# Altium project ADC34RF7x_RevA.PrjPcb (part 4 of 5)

## Sheet ADC34RF7x_Power3_RevA.SchDoc: EVM Power 3
size 431 x 279 mm; Date: Not shown in title block; ApprovedBy: Not shown in title block; CheckedBy: Not shown in title block; Author: Not shown in title block; CompanyName: Not shown in title block; DrawnBy: CW; Engineer: Not shown in title block; Organization: Not shown in title block; Address1: Not shown in title block; Address2: Not shown in title block; Address3: Not shown in title block; Address4: Not shown in title block; DocumentNumber: 7; Revision: Use project parameter SCH_Rev; SheetNumber: 15; SheetTotal: 19; PageSetup: Record=PageOptions¦CenterHorizontal=True¦CenterVertical=True¦PrintScale=1.00¦XCorrection=1.00¦YCorrection=1.00¦PrintKind=0¦BorderSize=5000000¦LeftOffset=0¦BottomOffset=0¦Orientation=2¦PaperLength=1000¦PaperWidth=1000¦Scale=100¦PaperSource=15¦PrintQuality=600¦MediaType=1¦DitherType=10¦PaperKind=Letter¦PrintScaleMode=1
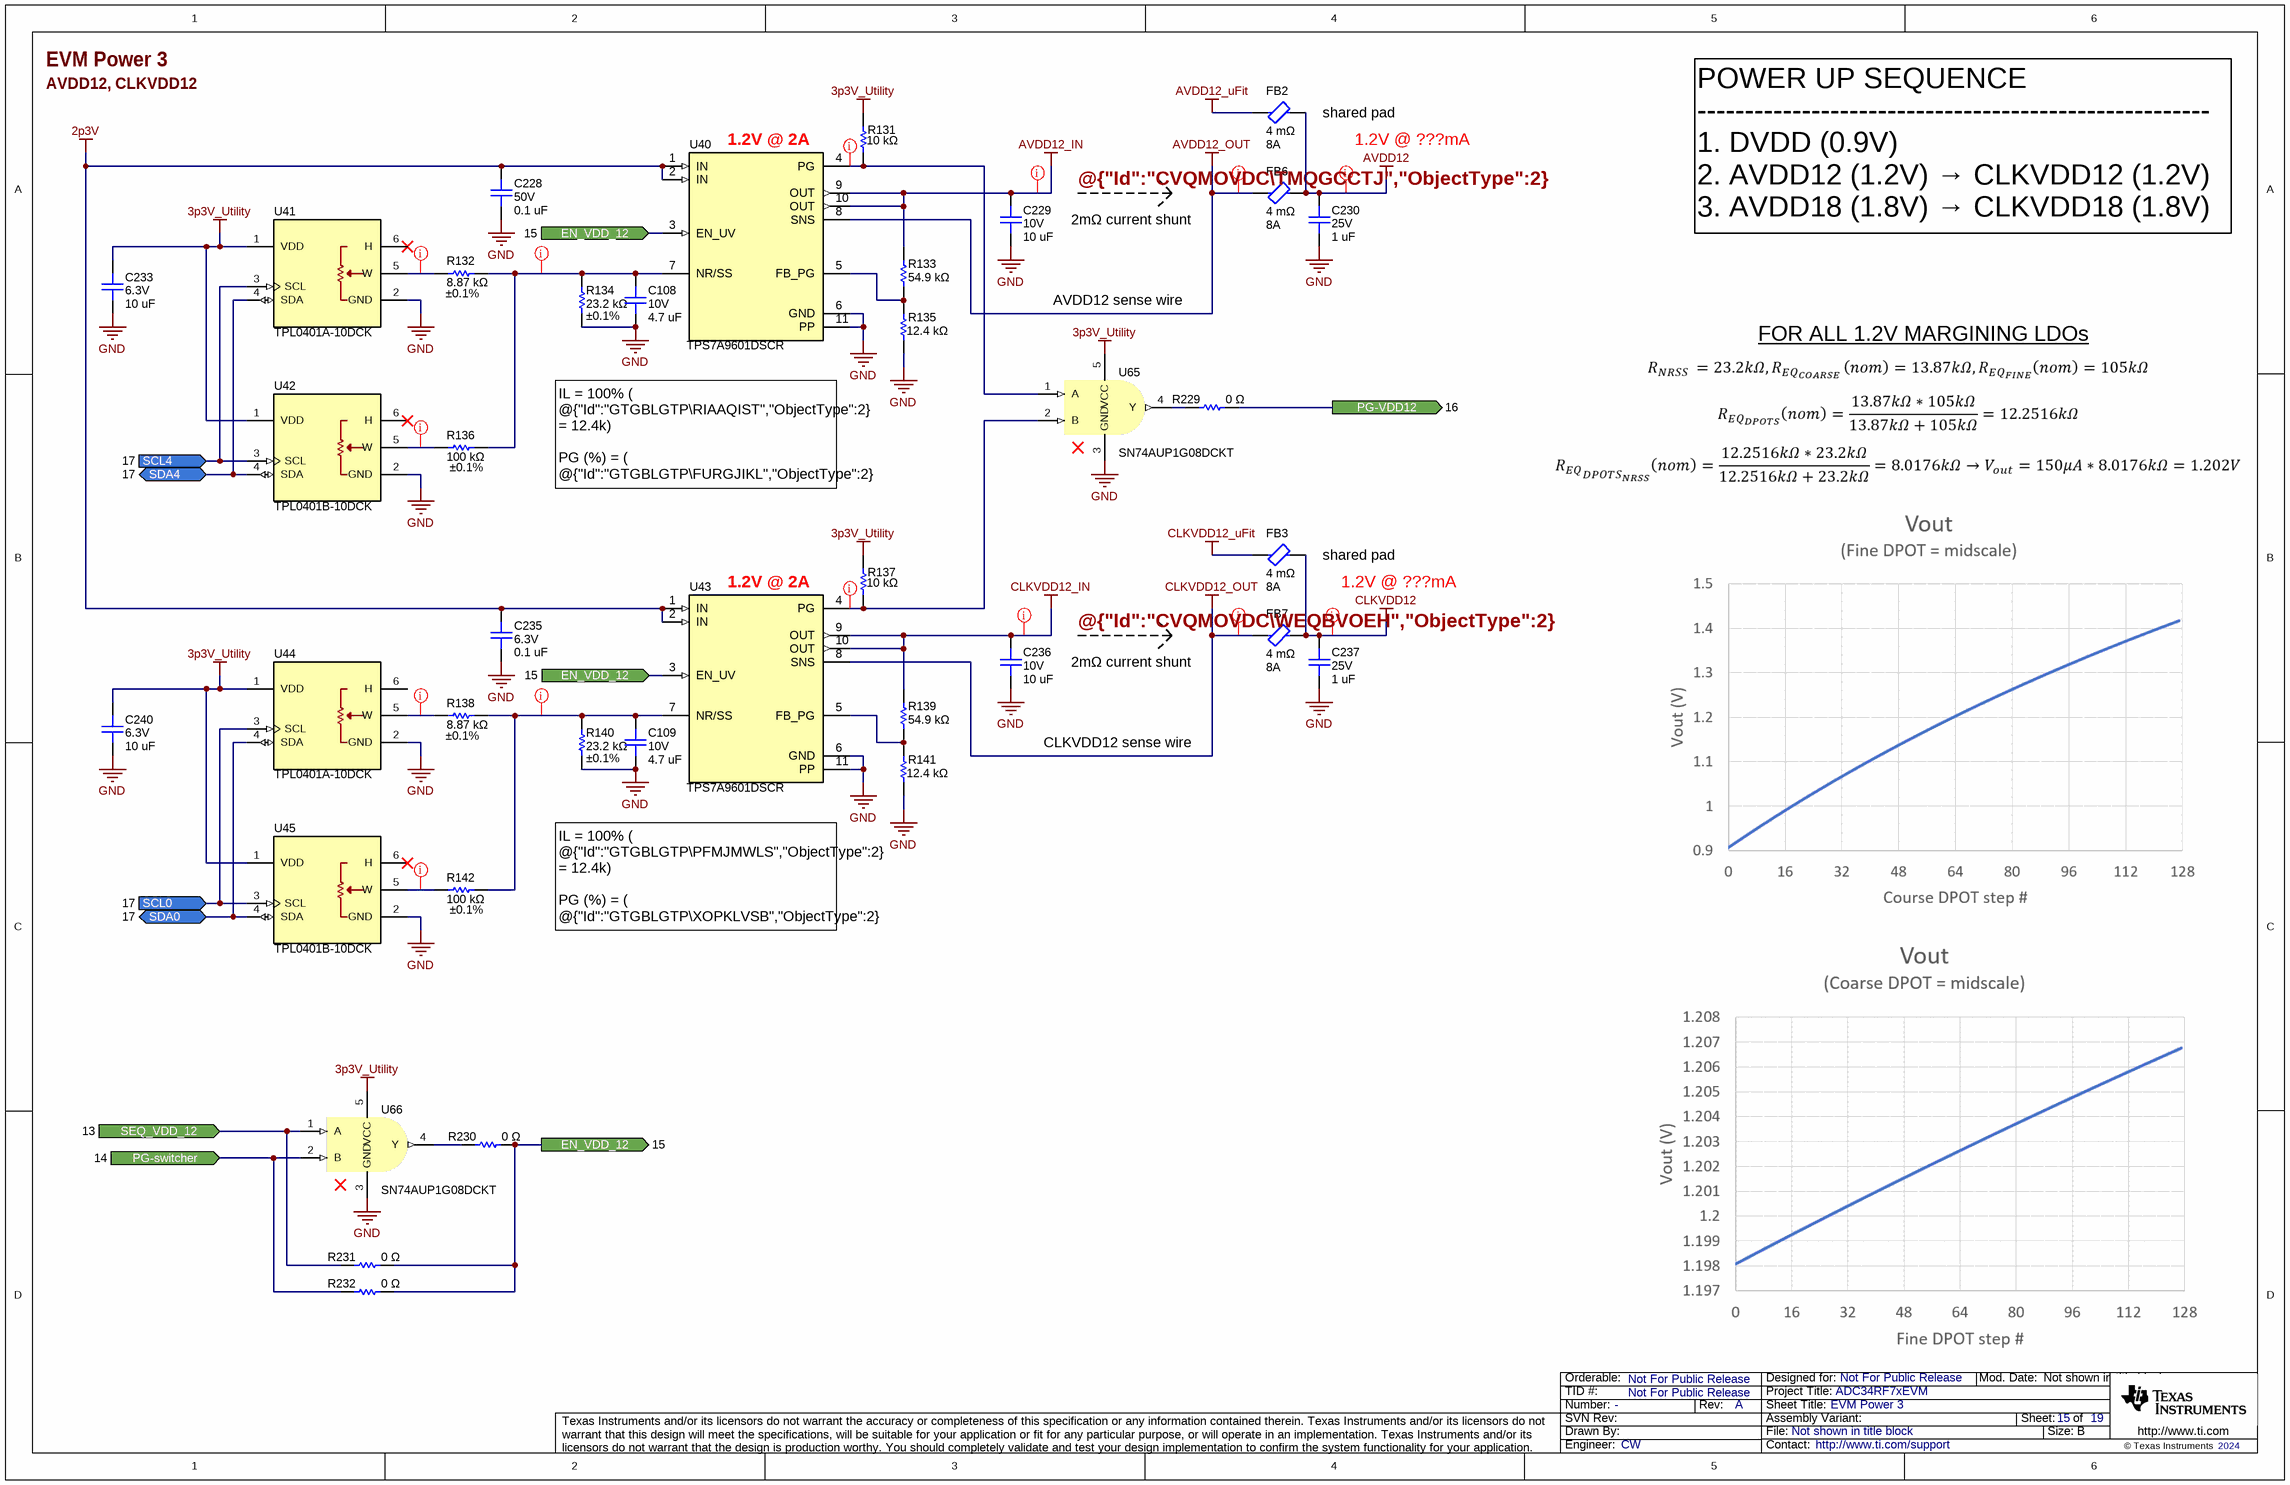
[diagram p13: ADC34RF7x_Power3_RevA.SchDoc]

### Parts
C108  value 4.7 uF  Voltage - Rated: 10V  [0402L_cap]  (hidden comment: C1005X5R1A475K050BE)
C109  value 4.7 uF  Voltage - Rated: 10V  [0402L_cap]  (hidden comment: C1005X5R1A475K050BE)
C228  value 0.1 uF  Voltage - Rated: 50V  [0402L_cap]  (hidden comment: C1005X5R1H104K050BB)
C229  value 10 uF  Voltage - Rated: 10V  [0603L_cap]  (hidden comment: 0603ZD106KAT2A)
C230  value 1 uF  Voltage - Rated: 25V  [0402L_cap]  (hidden comment: C1005X5R1E105K050BC)
C233  value 10 uF  Voltage - Rated: 6.3V  [0402L_cap]  (hidden comment: GRM155C80J106ME11D)
C235  value 0.1 uF  Voltage - Rated: 6.3V  [0402L_cap]  (hidden comment: 04026D104KAT4A)
C236  value 10 uF  Voltage - Rated: 10V  [0603L_cap]  (hidden comment: 0603ZD106KAT2A)
C237  value 1 uF  Voltage - Rated: 25V  [0402L_cap]  (hidden comment: C1005X5R1E105K050BC)
C240  value 10 uF  Voltage - Rated: 6.3V  [0402L_cap]  (hidden comment: GRM155C80J106ME11D)
FB2  Current: 8A  DCR: 4 mΩ  [0603L]  (hidden comment: BLE18PS080SN1D)
FB3  Current: 8A  DCR: 4 mΩ  [0603L]  (hidden comment: BLE18PS080SN1D)
FB6  Current: 8A  DCR: 4 mΩ  [0603L]  (hidden comment: BLE18PS080SN1D)
FB7  Current: 8A  DCR: 4 mΩ  [0603L]  (hidden comment: BLE18PS080SN1D)
R131  value 10 kΩ  [0402L]  (hidden comment: ERJ-PA2F1002X)
R132  value 8.87 kΩ  Tolerance: ±0.1%  [0402L]  (hidden comment: ERA-2AEB8871X)
R133  value 54.9 kΩ  [0402L]  (hidden comment: ERJ-2RKF5492X)
R134  value 23.2 kΩ  Tolerance: ±0.1%  [0402L]  (hidden comment: ERA-2ARB2322X)
R135  value 12.4 kΩ  [0402L]  (hidden comment: ERJ-2RKF1242X)
R136  value 100 kΩ  Tolerance: ±0.1%  [0402L]  (hidden comment: ERA-2AEB104X)
R137  value 10 kΩ  [0402L]  (hidden comment: ERJ-PA2F1002X)
R138  value 8.87 kΩ  Tolerance: ±0.1%  [0402L]  (hidden comment: ERA-2AEB8871X)
R139  value 54.9 kΩ  [0402L]  (hidden comment: ERJ-2RKF5492X)
R140  value 23.2 kΩ  Tolerance: ±0.1%  [0402L]  (hidden comment: ERA-2ARB2322X)
R141  value 12.4 kΩ  [0402L]  (hidden comment: ERJ-2RKF1242X)
R142  value 100 kΩ  Tolerance: ±0.1%  [0402L]  (hidden comment: ERA-2AEB104X)
R229  value 0 Ω  [0402L]  (hidden comment: ERJ-2GE0R00X)
R230  value 0 Ω  [0402L]  (hidden comment: ERJ-2GE0R00X)
R231  value 0 Ω  [0402L]  (hidden comment: ERJ-2GE0R00X)
R232  value 0 Ω  [0402L]  (hidden comment: ERJ-2GE0R00X)
U40  PartNumber: TPS7A9601DSCR  [DRC0010J]  (hidden comment: TPS7A9601DSC)
U41  TPL0401A-10DCK  [DCK0006A]
U42  TPL0401B-10DCK  [DCK0006A]
U43  PartNumber: TPS7A9601DSCR  [DRC0010J]  (hidden comment: TPS7A9601DSC)
U44  TPL0401A-10DCK  [DCK0006A]
U45  TPL0401B-10DCK  [DCK0006A]
U65  SN74AUP1G08DCKT  [DCK0005A]
U66  SN74AUP1G08DCKT  [DCK0005A]

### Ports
EN_VDD_12 (in, see 15), EN_VDD_12 (out, see 15), PG-switcher (in, see 14), PG-VDD12 (out, see 16), SCL0 (in, see 17), SCL4 (in, see 17), SDA0 (bidir, see 17), SDA4 (bidir, see 17), SEQ_VDD_12 (in, see 13)

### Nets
2p3V: C228.2 C235.2 U40.1(IN) U40.2(IN) U43.1(IN) U43.2(IN)
3p3V_Utility: C233.2 C240.2 R131.2 R137.2 U41.1(VDD) U42.1(VDD) U44.1(VDD) U45.1(VDD) U65.5(VCC) U66.5(VCC)
AVDD12: C230.2 FB2.2 FB6.2
AVDD12_IN: C229.2 R133.2 U40.9(OUT) U40.10(OUT)
AVDD12_OUT: FB6.1 U40.8(SNS)
AVDD12_uFit: FB2.1
CLKVDD12: C237.2 FB3.2 FB7.2
CLKVDD12_IN: C236.2 R139.2 U43.9(OUT) U43.10(OUT)
CLKVDD12_OUT: FB7.1 U43.8(SNS)
CLKVDD12_uFit: FB3.1
GND: C108.2 C109.2 C228.1 C229.1 C230.1 C233.1 C235.1 C236.1 C237.1 C240.1 R134.1 R135.1 R140.1 R141.1 U40.6(GND) U40.11(PP) U41.2(GND) U42.2(GND) U43.6(GND) U43.11(PP) U44.2(GND) U45.2(GND) U65.3(GND) U66.3(GND)
EN_VDD_12: R230.2 R231.2 R232.2 U40.3(EN_UV) U43.3(EN_UV) ; port EN_VDD_12
PG-switcher: R232.1 U66.2(B) ; port PG-switcher
PG-VDD12: R229.2 ; port PG-VDD12
SCL0: U44.3(SCL) U45.3(SCL) ; port SCL0
SCL4: U41.3(SCL) U42.3(SCL) ; port SCL4
SDA0: U44.4(SDA) U45.4(SDA) ; port SDA0
SDA4: U41.4(SDA) U42.4(SDA) ; port SDA4
SEQ_VDD_12: R231.1 U66.1(A) ; port SEQ_VDD_12
NetC108_1: C108.1 R132.2 R134.2 R136.2 U40.7(NR/SS)
NetC109_1: C109.1 R138.2 R140.2 R142.2 U43.7(NR/SS)
NetR131_1: R131.1 U40.4(PG) U65.1(A)
NetR132_1: R132.1 U41.5(W)
NetR133_1: R133.1 R135.2 U40.5(FB_PG)
NetR136_1: R136.1 U42.5(W)
NetR137_1: R137.1 U43.4(PG) U65.2(B)
NetR138_1: R138.1 U44.5(W)
NetR139_1: R139.1 R141.2 U43.5(FB_PG)
NetR142_1: R142.1 U45.5(W)
NetR229_1: R229.1 U65.4(Y)
NetR230_1: R230.1 U66.4(Y)

Not connected (* = marked no-connect by the designer): U41 6(H)*; U42 6(H)*; U44 6(H); U45 6(H)*

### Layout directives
net class Power_AVDD12: AVDD12, AVDD12_IN, AVDD12_OUT
net class Power_CLKVDD12: CLKVDD12, CLKVDD12_IN, CLKVDD12_OUT
net class Power sequencing: NetR131_1, NetR137_1
net class Margining: NetC108_1, NetC109_1, NetR132_1, NetR136_1, NetR138_1, NetR142_1

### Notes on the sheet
- AVDD12, CLKVDD12
- (near U40) 1.2V @ 2A
- (near FB2) shared pad
- 1.2V @ ???mA
- @{"Id":"CVQMOVDC\TMQGCCTJ","ObjectType":2}
- 2mΩ current shunt
- POWER UP SEQUENCE
  ------------------------------------------------------
  1. DVDD (0.9V)
  2. AVDD12 (1.2V) → CLKVDD12 (1.2V)
  3. AVDD18 (1.8V) → CLKVDD18 (1.8V)
- AVDD12 sense wire
- FOR ALL 1.2V MARGINING LDOs
- IL = 100% ( @{"Id":"GTGBLGTP\RIAAQIST","ObjectType":2} = 12.4k)
  PG (%) = ( @{"Id":"GTGBLGTP\FURGJIKL","ObjectType":2} / @{"Id":"GTGBLGTP\RIAAQIST","ObjectType":2} +1)*(0.2V/1.2V)
  PG (%) = (54.9k/12.4k+1)*(0.2V/1.2V)
  PG = 90.4%
- (near FB3) shared pad
- (near U43) 1.2V @ 2A
- @{"Id":"CVQMOVDC\WEQBVOEH","ObjectType":2}
- CLKVDD12 sense wire
- IL = 100% ( @{"Id":"GTGBLGTP\PFMJMWLS","ObjectType":2} = 12.4k)
  PG (%) = ( @{"Id":"GTGBLGTP\XOPKLVSB","ObjectType":2} / @{"Id":"GTGBLGTP\PFMJMWLS","ObjectType":2} +1)*(0.2V/1.2V)
  PG (%) = (54.9k/12.4k+1)*(0.2V/1.2V)
  PG = 90.4%

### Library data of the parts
C108 C109 = capcc03139: CAP CER 4.7UF 10V X5R 0402; Manufacturer: TDK Corporation; CompType: Capacitor Ceramic; Tolerance: ±10%; SizeX_mm: 1; SizeY_mm: 0.5; SizeZ_mm: 0.7
C228 = capcc01268: CAP CER 0.1UF 50V X5R 0402; Manufacturer: TDK Corporation; CompType: Capacitor Ceramic; Tolerance: ±10%; SizeX_mm: 1; SizeY_mm: 0.5; SizeZ_mm: 0.55
C229 C236 = capcc03657: CAP CER 10UF 10V X5R 0603; Manufacturer: KYOCERA AVX; CompType: Capacitor Ceramic; Tolerance: ±10%; SizeX_mm: 1.6; SizeY_mm: 0.81; SizeZ_mm: 0.94
C230 C237 = capcc02750: CAP CER 1UF 25V X5R 0402; Manufacturer: TDK Corporation; CompType: Capacitor Ceramic; Tolerance: ±10%; SizeX_mm: 1; SizeY_mm: 0.5; SizeZ_mm: 0.55
C233 C240 = capcc09398: CAP CER 10UF 6.3V X6S 0402; Manufacturer: Murata; CompType: Capacitor Ceramic; Tolerance: ±20%; SizeX_mm: 1; SizeY_mm: 0.5; SizeZ_mm: 0.7
C235 = capcc01277: CAP CER 0.1UF 6.3V X5R 0402; Manufacturer: KYOCERA AVX; CompType: Capacitor Ceramic; Tolerance: ±10%; SizeX_mm: 1; SizeY_mm: 0.5
FB2 FB3 FB6 FB7 = dcp00004: 8.5 Ohms @ 100 MHz 1 Power Line Ferrite Bead 0603 (1608 Metric) 8A 4mOhm; Manufacturer: Murata; Impedance: 8.5 Ω; SizeX_mm: 1.6; SizeY_mm: 0.8
R131 R137 = RSMD040200311: RES SMD 10K OHM 1% 1/5W 0402; Manufacturer: Panasonic Electronic Components; SizeX_mm: 1; SizeY_mm: 0.5; SizeZ_mm: 0.4; CompType: Resistor SMD; Power (Watts): 0.2W, 1/5W; Temperature Coefficient: ±100ppm/°C
R132 R138 = RSMD040203743: RES SMD 8.87KOHM 0.1% 1/16W 0402; Manufacturer: Panasonic Electronic Components; CompType: Resistor SMD; Power (Watts): 0.063W, 1/16W; Temperature Coefficient: ±25ppm/°C; SizeX_mm: 1; SizeY_mm: 0.5; SizeZ_mm: 0.4
R133 R139 = RSMD040203107: RES SMD 54.9K OHM 1% 1/10W 0402; Manufacturer: Panasonic Electronic Components; CompType: Resistor SMD; Power (Watts): 0.1W, 1/10W; Temperature Coefficient: ±100ppm/°C; SizeX_mm: 1; SizeY_mm: 0.5; SizeZ_mm: 0.4
R134 R140 = RSMD040201567: RES SMD 23.2KOHM 0.1% 1/16W 0402; Manufacturer: Panasonic Electronic Components; CompType: Resistor SMD; Power (Watts): 0.063W, 1/16W; Temperature Coefficient: ±10ppm/°C; SizeX_mm: 1; SizeY_mm: 0.5; SizeZ_mm: 0.4
R135 R141 = RSMD040200547: RES SMD 12.4K OHM 1% 1/10W 0402; Manufacturer: Panasonic Electronic Components; CompType: Resistor SMD; Power (Watts): 0.1W, 1/10W; Temperature Coefficient: ±100ppm/°C; SizeX_mm: 1; SizeY_mm: 0.5; SizeZ_mm: 0.4
R136 R142 = RSMD040200357: RES SMD 100K OHM 0.1% 1/16W 0402; Manufacturer: Panasonic Electronic Components; CompType: Resistor SMD; Power (Watts): 0.063W, 1/16W; Temperature Coefficient: ±25ppm/°C; SizeX_mm: 1; SizeY_mm: 0.5; SizeZ_mm: 0.4
R229-R232 = RSMD040200001: RES SMD 0 OHM JUMPER 1/10W 0402; Manufacturer: Panasonic Electronic Components; CompType: Resistor SMD; Power (Watts): 0.1W, 1/10W; SizeX_mm: 1; SizeY_mm: 0.5; SizeZ_mm: 0.4
U40 U43 = cmp00446: 2-A, ultra-low noise ultra-high PSRR RF voltage regulator; Manufacturer: Texas Instruments; CompType: LDO
U41 U44 = TPL0401A-10DCK: 128-tap single-channel digital potentiometer (digipot) with I2C interface (address 0101110); Alternate PartNumber: TPL0401A-10DCKT; Manufacturer: Texas Instruments; SymbolCreator: Altium; SizeArea_mm2: 4.2; SizeAreaWB_mm2: 9.3; U/M: EA; UniqueID: cmp00230
U42 U45 = TPL0401B-10DCK: 128-tap single-channel digital potentiometer (digipot) with I2C interface (address 0111110); Alternate PartNumber: TPL0401B-10DCKT; Manufacturer: Texas Instruments; SymbolCreator: Altium; SizeArea_mm2: 4.2; SizeAreaWB_mm2: 9.3; U/M: EA; UniqueID: cmp00231
U65 U66 = cmp00268: SN74AUP1G08 Low-Power Single 2-Input Positive-AND Gate; Manufacturer: Texas Instruments

## Sheet ADC34RF7x_Power4_RevA.SchDoc: EVM Power 4
size 431 x 279 mm; Date: Not shown in title block; ApprovedBy: Not shown in title block; CheckedBy: Not shown in title block; Author: Not shown in title block; CompanyName: Not shown in title block; DrawnBy: CW; Engineer: Not shown in title block; Organization: Not shown in title block; Address1: Not shown in title block; Address2: Not shown in title block; Address3: Not shown in title block; Address4: Not shown in title block; DocumentNumber: 8; Revision: Use project parameter SCH_Rev; SheetNumber: 16; SheetTotal: 19; PageSetup: Record=PageOptions¦CenterHorizontal=True¦CenterVertical=True¦PrintScale=1.00¦XCorrection=1.00¦YCorrection=1.00¦PrintKind=0¦BorderSize=5000000¦LeftOffset=0¦BottomOffset=0¦Orientation=2¦PaperLength=1000¦PaperWidth=1000¦Scale=100¦PaperSource=15¦PrintQuality=600¦MediaType=1¦DitherType=10¦PaperKind=Letter¦PrintScaleMode=1
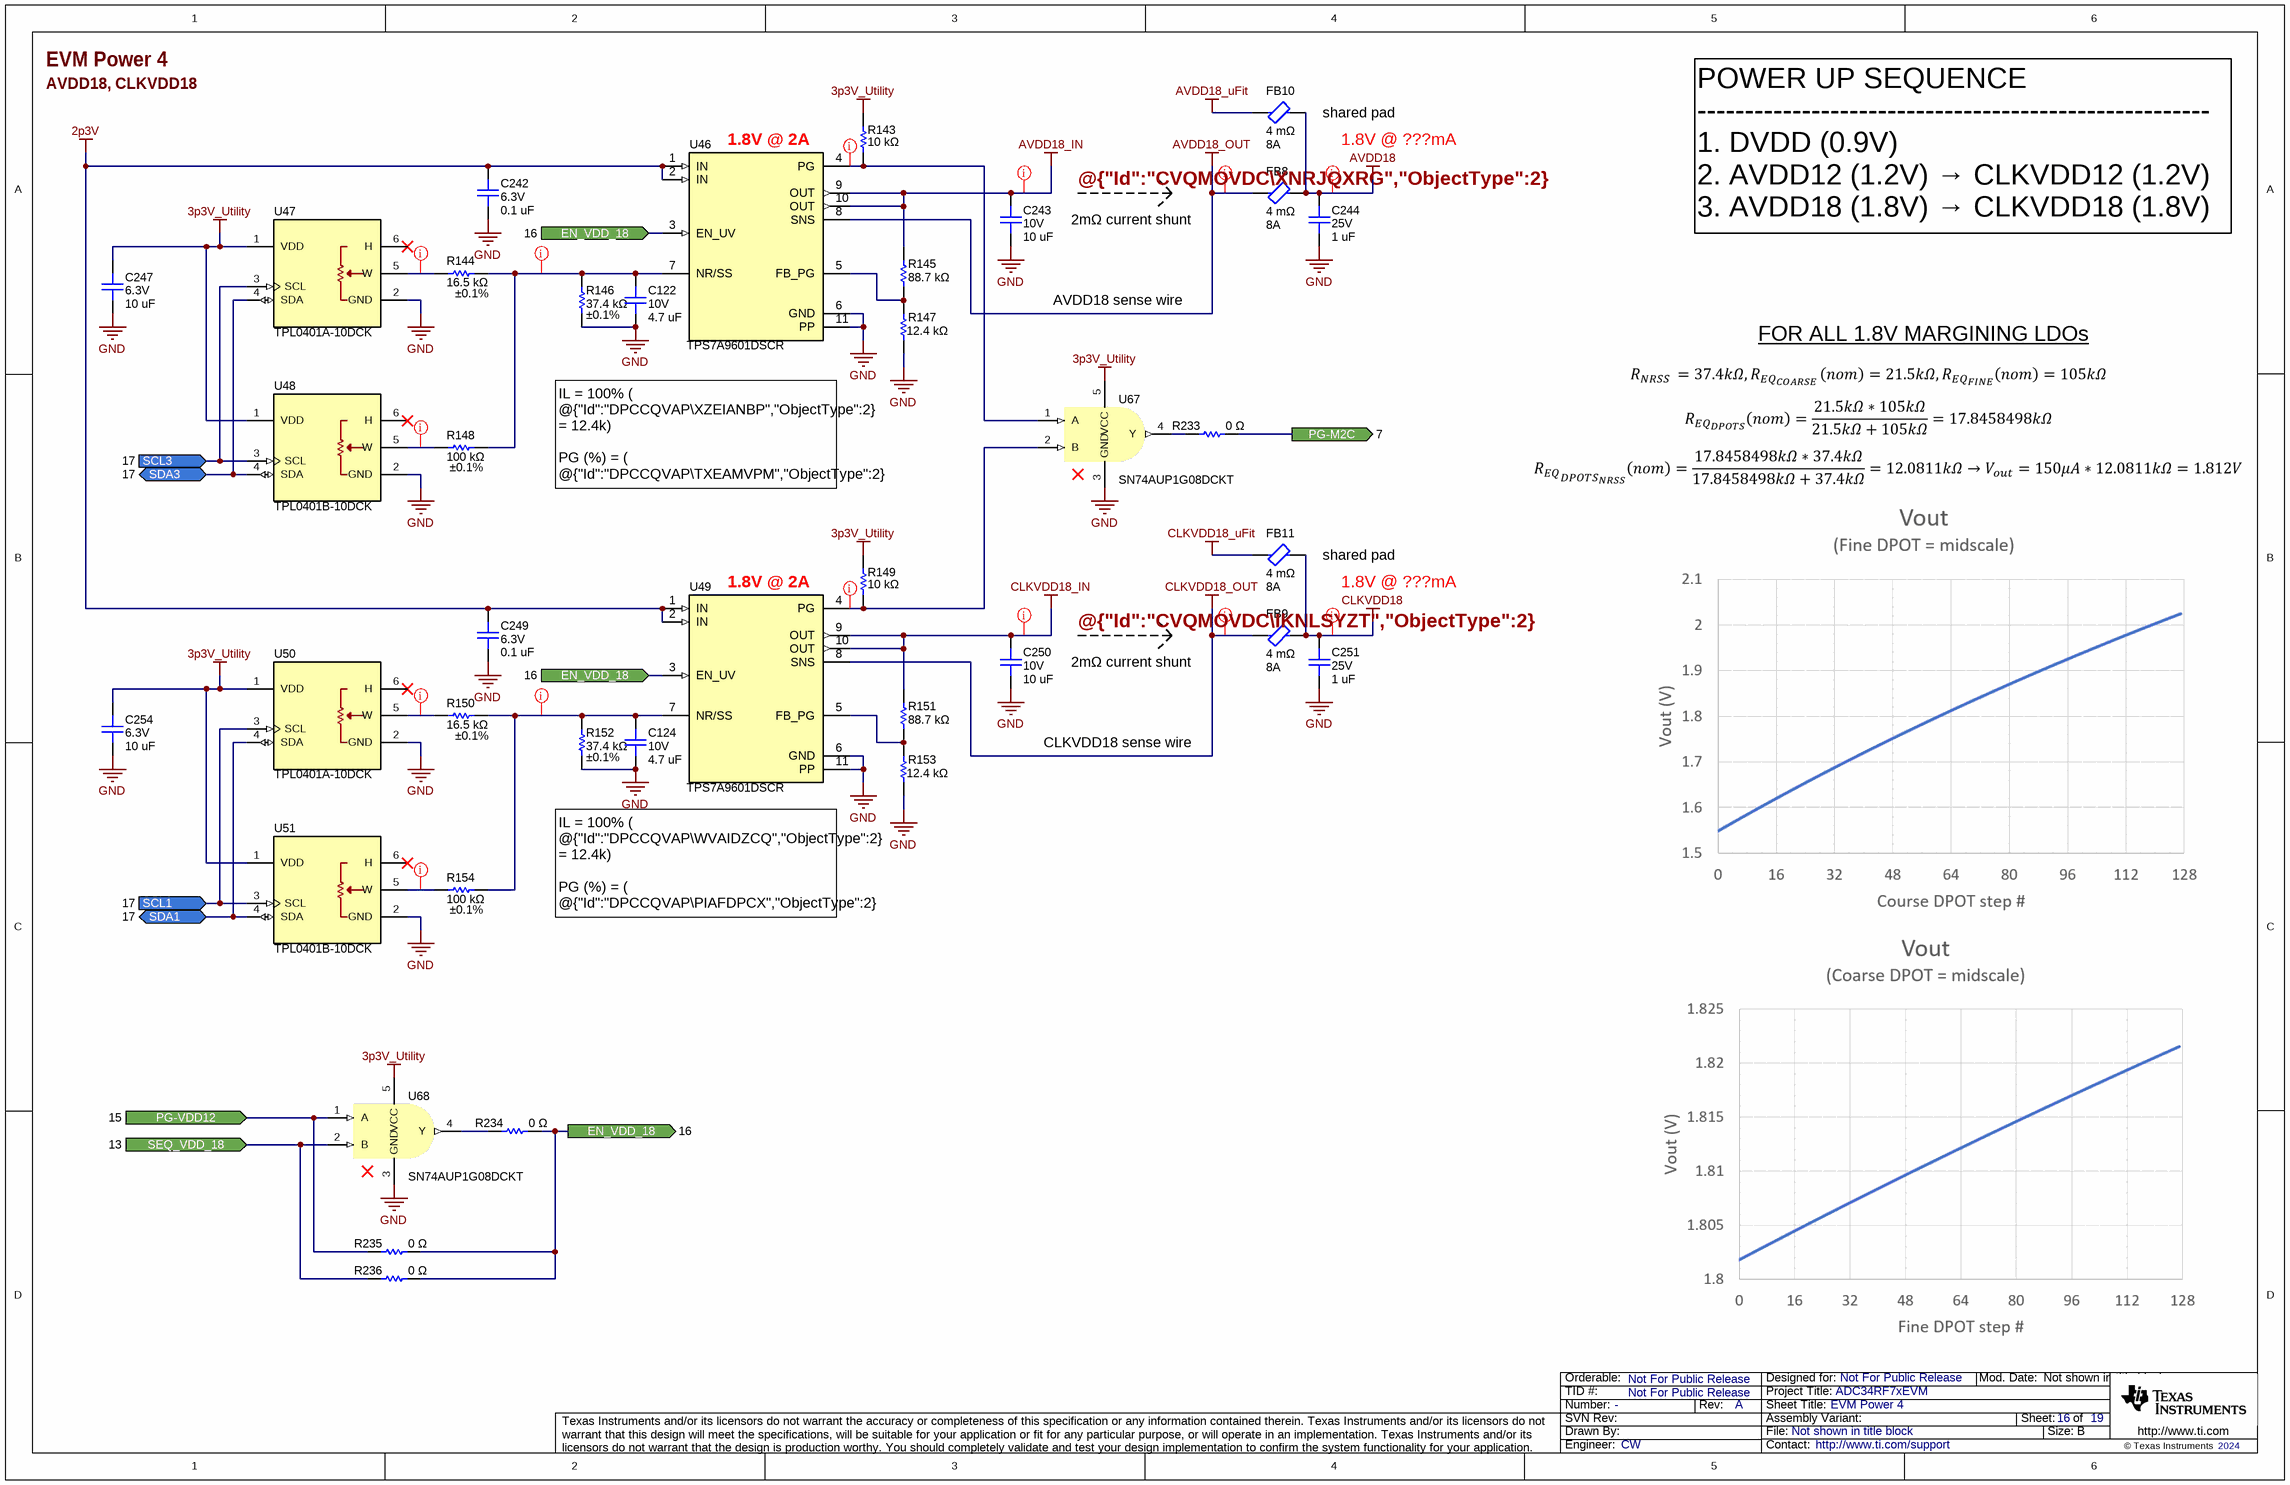
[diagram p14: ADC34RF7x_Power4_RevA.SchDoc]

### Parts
C122  value 4.7 uF  Voltage - Rated: 10V  [0402L_cap]  (hidden comment: C1005X5R1A475K050BE)
C124  value 4.7 uF  Voltage - Rated: 10V  [0402L_cap]  (hidden comment: C1005X5R1A475K050BE)
C242  value 0.1 uF  Voltage - Rated: 6.3V  [0402L_cap]  (hidden comment: 04026D104KAT4A)
C243  value 10 uF  Voltage - Rated: 10V  [0603L_cap]  (hidden comment: 0603ZD106KAT2A)
C244  value 1 uF  Voltage - Rated: 25V  [0402L_cap]  (hidden comment: C1005X5R1E105K050BC)
C247  value 10 uF  Voltage - Rated: 6.3V  [0402L_cap]  (hidden comment: GRM155C80J106ME11D)
C249  value 0.1 uF  Voltage - Rated: 6.3V  [0402L_cap]  (hidden comment: 04026D104KAT4A)
C250  value 10 uF  Voltage - Rated: 10V  [0603L_cap]  (hidden comment: 0603ZD106KAT2A)
C251  value 1 uF  Voltage - Rated: 25V  [0402L_cap]  (hidden comment: C1005X5R1E105K050BC)
C254  value 10 uF  Voltage - Rated: 6.3V  [0402L_cap]  (hidden comment: GRM155C80J106ME11D)
FB8  Current: 8A  DCR: 4 mΩ  [0603L]  (hidden comment: BLE18PS080SN1D)
FB9  Current: 8A  DCR: 4 mΩ  [0603L]  (hidden comment: BLE18PS080SN1D)
FB10  Current: 8A  DCR: 4 mΩ  [0603L]  (hidden comment: BLE18PS080SN1D)
FB11  Current: 8A  DCR: 4 mΩ  [0603L]  (hidden comment: BLE18PS080SN1D)
R143  value 10 kΩ  [0402L]  (hidden comment: ERJ-PA2F1002X)
R144  value 16.5 kΩ  Tolerance: ±0.1%  [0402L]  (hidden comment: ERA-2ARB1652X)
R145  value 88.7 kΩ  [0402L]  (hidden comment: ERA-2AEB8872X)
R146  value 37.4 kΩ  Tolerance: ±0.1%  [0402L]  (hidden comment: ERA-2ARB3742X)
R147  value 12.4 kΩ  [0402L]  (hidden comment: ERJ-2RKF1242X)
R148  value 100 kΩ  Tolerance: ±0.1%  [0402L]  (hidden comment: ERA-2AEB104X)
R149  value 10 kΩ  [0402L]  (hidden comment: ERJ-PA2F1002X)
R150  value 16.5 kΩ  Tolerance: ±0.1%  [0402L]  (hidden comment: ERA-2ARB1652X)
R151  value 88.7 kΩ  [0402L]  (hidden comment: ERA-2AEB8872X)
R152  value 37.4 kΩ  Tolerance: ±0.1%  [0402L]  (hidden comment: ERA-2ARB3742X)
R153  value 12.4 kΩ  [0402L]  (hidden comment: ERJ-2RKF1242X)
R154  value 100 kΩ  Tolerance: ±0.1%  [0402L]  (hidden comment: ERA-2AEB104X)
R233  value 0 Ω  [0402L]  (hidden comment: ERJ-2GE0R00X)
R234  value 0 Ω  [0402L]  (hidden comment: ERJ-2GE0R00X)
R235  value 0 Ω  [0402L]  (hidden comment: ERJ-2GE0R00X)
R236  value 0 Ω  [0402L]  (hidden comment: ERJ-2GE0R00X)
U46  PartNumber: TPS7A9601DSCR  [DRC0010J]  (hidden comment: TPS7A9601DSC)
U47  TPL0401A-10DCK  [DCK0006A]
U48  TPL0401B-10DCK  [DCK0006A]
U49  PartNumber: TPS7A9601DSCR  [DRC0010J]  (hidden comment: TPS7A9601DSC)
U50  TPL0401A-10DCK  [DCK0006A]
U51  TPL0401B-10DCK  [DCK0006A]
U67  SN74AUP1G08DCKT  [DCK0005A]
U68  SN74AUP1G08DCKT  [DCK0005A]

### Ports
EN_VDD_18 (in, see 16), EN_VDD_18 (out, see 16), PG-M2C (out, see 7), PG-VDD12 (in, see 15), SCL1 (in, see 17), SCL3 (in, see 17), SDA1 (bidir, see 17), SDA3 (bidir, see 17), SEQ_VDD_18 (in, see 13)

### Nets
2p3V: C242.2 C249.2 U46.1(IN) U46.2(IN) U49.1(IN) U49.2(IN)
3p3V_Utility: C247.2 C254.2 R143.2 R149.2 U47.1(VDD) U48.1(VDD) U50.1(VDD) U51.1(VDD) U67.5(VCC) U68.5(VCC)
AVDD18: C244.2 FB8.2 FB10.2
AVDD18_IN: C243.2 R145.2 U46.9(OUT) U46.10(OUT)
AVDD18_OUT: FB8.1 U46.8(SNS)
AVDD18_uFit: FB10.1
CLKVDD18: C251.2 FB9.2 FB11.2
CLKVDD18_IN: C250.2 R151.2 U49.9(OUT) U49.10(OUT)
CLKVDD18_OUT: FB9.1 U49.8(SNS)
CLKVDD18_uFit: FB11.1
GND: C122.2 C124.2 C242.1 C243.1 C244.1 C247.1 C249.1 C250.1 C251.1 C254.1 R146.1 R147.1 R152.1 R153.1 U46.6(GND) U46.11(PP) U47.2(GND) U48.2(GND) U49.6(GND) U49.11(PP) U50.2(GND) U51.2(GND) U67.3(GND) U68.3(GND)
EN_VDD_18: R234.2 R235.2 R236.2 U46.3(EN_UV) U49.3(EN_UV) ; port EN_VDD_18
PG-M2C: R233.2 ; port PG-M2C
PG-VDD12: R235.1 U68.1(A) ; port PG-VDD12
SCL1: U50.3(SCL) U51.3(SCL) ; port SCL1
SCL3: U47.3(SCL) U48.3(SCL) ; port SCL3
SDA1: U50.4(SDA) U51.4(SDA) ; port SDA1
SDA3: U47.4(SDA) U48.4(SDA) ; port SDA3
SEQ_VDD_18: R236.1 U68.2(B) ; port SEQ_VDD_18
NetC122_1: C122.1 R144.1 R146.2 R148.2 U46.7(NR/SS)
NetC124_1: C124.1 R150.1 R152.2 R154.2 U49.7(NR/SS)
NetR143_1: R143.1 U46.4(PG) U67.1(A)
NetR144_2: R144.2 U47.5(W)
NetR145_1: R145.1 R147.2 U46.5(FB_PG)
NetR148_1: R148.1 U48.5(W)
NetR149_1: R149.1 U49.4(PG) U67.2(B)
NetR150_2: R150.2 U50.5(W)
NetR151_1: R151.1 R153.2 U49.5(FB_PG)
NetR154_1: R154.1 U51.5(W)
NetR233_1: R233.1 U67.4(Y)
NetR234_1: R234.1 U68.4(Y)

Not connected (* = marked no-connect by the designer): U47 6(H)*; U48 6(H)*; U50 6(H)*; U51 6(H)*

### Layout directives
net class Power_AVDD18: AVDD18, AVDD18_IN, AVDD18_OUT
net class Power_CLKVDD18: CLKVDD18, CLKVDD18_IN, CLKVDD18_OUT
net class Power sequencing: NetR143_1, NetR149_1
net class Margining: NetC122_1, NetC124_1, NetR144_2, NetR148_1, NetR150_2, NetR154_1

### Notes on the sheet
- AVDD18, CLKVDD18
- (near U46) 1.8V @ 2A
- (near FB10) shared pad
- 1.8V @ ???mA
- @{"Id":"CVQMOVDC\XNRJQXRG","ObjectType":2}
- 2mΩ current shunt
- POWER UP SEQUENCE
  ------------------------------------------------------
  1. DVDD (0.9V)
  2. AVDD12 (1.2V) → CLKVDD12 (1.2V)
  3. AVDD18 (1.8V) → CLKVDD18 (1.8V)
- AVDD18 sense wire
- FOR ALL 1.8V MARGINING LDOs
- IL = 100% ( @{"Id":"DPCCQVAP\XZEIANBP","ObjectType":2} = 12.4k)
  PG (%) = ( @{"Id":"DPCCQVAP\TXEAMVPM","ObjectType":2} / @{"Id":"DPCCQVAP\XZEIANBP","ObjectType":2} +1)*(0.2V/1.8V)
  PG (%) = (88.7k/12.4k+1)*(0.2V/1.8V)
  PG = 90.6%
- (near FB11) shared pad
- (near U49) 1.8V @ 2A
- @{"Id":"CVQMOVDC\IKNLSYZT","ObjectType":2}
- CLKVDD18 sense wire
- IL = 100% ( @{"Id":"DPCCQVAP\WVAIDZCQ","ObjectType":2} = 12.4k)
  PG (%) = ( @{"Id":"DPCCQVAP\PIAFDPCX","ObjectType":2} / @{"Id":"DPCCQVAP\WVAIDZCQ","ObjectType":2} +1)*(0.2V/1.8V)
  PG (%) = (88.7k/12.4k+1)*(0.2V/1.8V)
  PG = 90.6%

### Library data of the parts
C122 C124 = capcc03139: as C108 on sheet ADC34RF7x_Power3_RevA
C242 C249 = capcc01277: as C235 on sheet ADC34RF7x_Power3_RevA
C243 C250 = capcc03657: as C229 on sheet ADC34RF7x_Power3_RevA
C244 C251 = capcc02750: as C230 on sheet ADC34RF7x_Power3_RevA
C247 C254 = capcc09398: as C233 on sheet ADC34RF7x_Power3_RevA
FB8-FB11 = dcp00004: as FB2 on sheet ADC34RF7x_Power3_RevA
R143 R149 = RSMD040200311: as R131 on sheet ADC34RF7x_Power3_RevA
R144 R150 = RSMD040200901: RES SMD 16.5KOHM 0.1% 1/16W 0402; Manufacturer: Panasonic Electronic Components; CompType: Resistor SMD; Power (Watts): 0.063W, 1/16W; Temperature Coefficient: ±10ppm/°C; SizeX_mm: 1; SizeY_mm: 0.5; SizeZ_mm: 0.4
R145 R151 = RSMD040203878: RES SMD 88.7KOHM 0.1% 1/16W 0402; Manufacturer: Panasonic Electronic Components; CompType: Resistor SMD; Power (Watts): 0.063W, 1/16W; Temperature Coefficient: ±25ppm/°C; SizeX_mm: 1; SizeY_mm: 0.5; SizeZ_mm: 0.4
R146 R152 = RSMD040202420: RES SMD 37.4KOHM 0.1% 1/16W 0402; Manufacturer: Panasonic Electronic Components; CompType: Resistor SMD; Power (Watts): 0.063W, 1/16W; Temperature Coefficient: ±10ppm/°C; SizeX_mm: 1; SizeY_mm: 0.5; SizeZ_mm: 0.4
R147 R153 = RSMD040200547: as R135 on sheet ADC34RF7x_Power3_RevA
R148 R154 = RSMD040200357: as R136 on sheet ADC34RF7x_Power3_RevA
R233-R236 = RSMD040200001: as R229-R232 on sheet ADC34RF7x_Power3_RevA
U46 U49 = cmp00446: as U40 on sheet ADC34RF7x_Power3_RevA
U47 U50 = TPL0401A-10DCK: as U41 on sheet ADC34RF7x_Power3_RevA
U48 U51 = TPL0401B-10DCK: as U42 on sheet ADC34RF7x_Power3_RevA
U67 U68 = cmp00268: as U65 on sheet ADC34RF7x_Power3_RevA

## Sheet ADC34RF7x_I2C_Shunts_Margining.SchDoc: I2C Devices
size 431 x 279 mm; Date: Not shown in title block; ApprovedBy: Not shown in title block; CheckedBy: Not shown in title block; Author: Not shown in title block; CompanyName: Not shown in title block; DrawnBy: CW; Engineer: Not shown in title block; Organization: Not shown in title block; Address1: Not shown in title block; Address2: Not shown in title block; Address3: Not shown in title block; Address4: Not shown in title block; DocumentNumber: 7; Revision: Use project parameter SCH_Rev; SheetNumber: 16; SheetTotal: 19; PageSetup: Record=PageOptions¦CenterHorizontal=True¦CenterVertical=True¦PrintScale=1.00¦XCorrection=1.00¦YCorrection=1.00¦PrintKind=0¦BorderSize=5000000¦LeftOffset=0¦BottomOffset=0¦Orientation=2¦PaperLength=1000¦PaperWidth=1000¦Scale=100¦PaperSource=15¦PrintQuality=600¦MediaType=1¦DitherType=10¦PaperKind=Letter¦PrintScaleMode=1
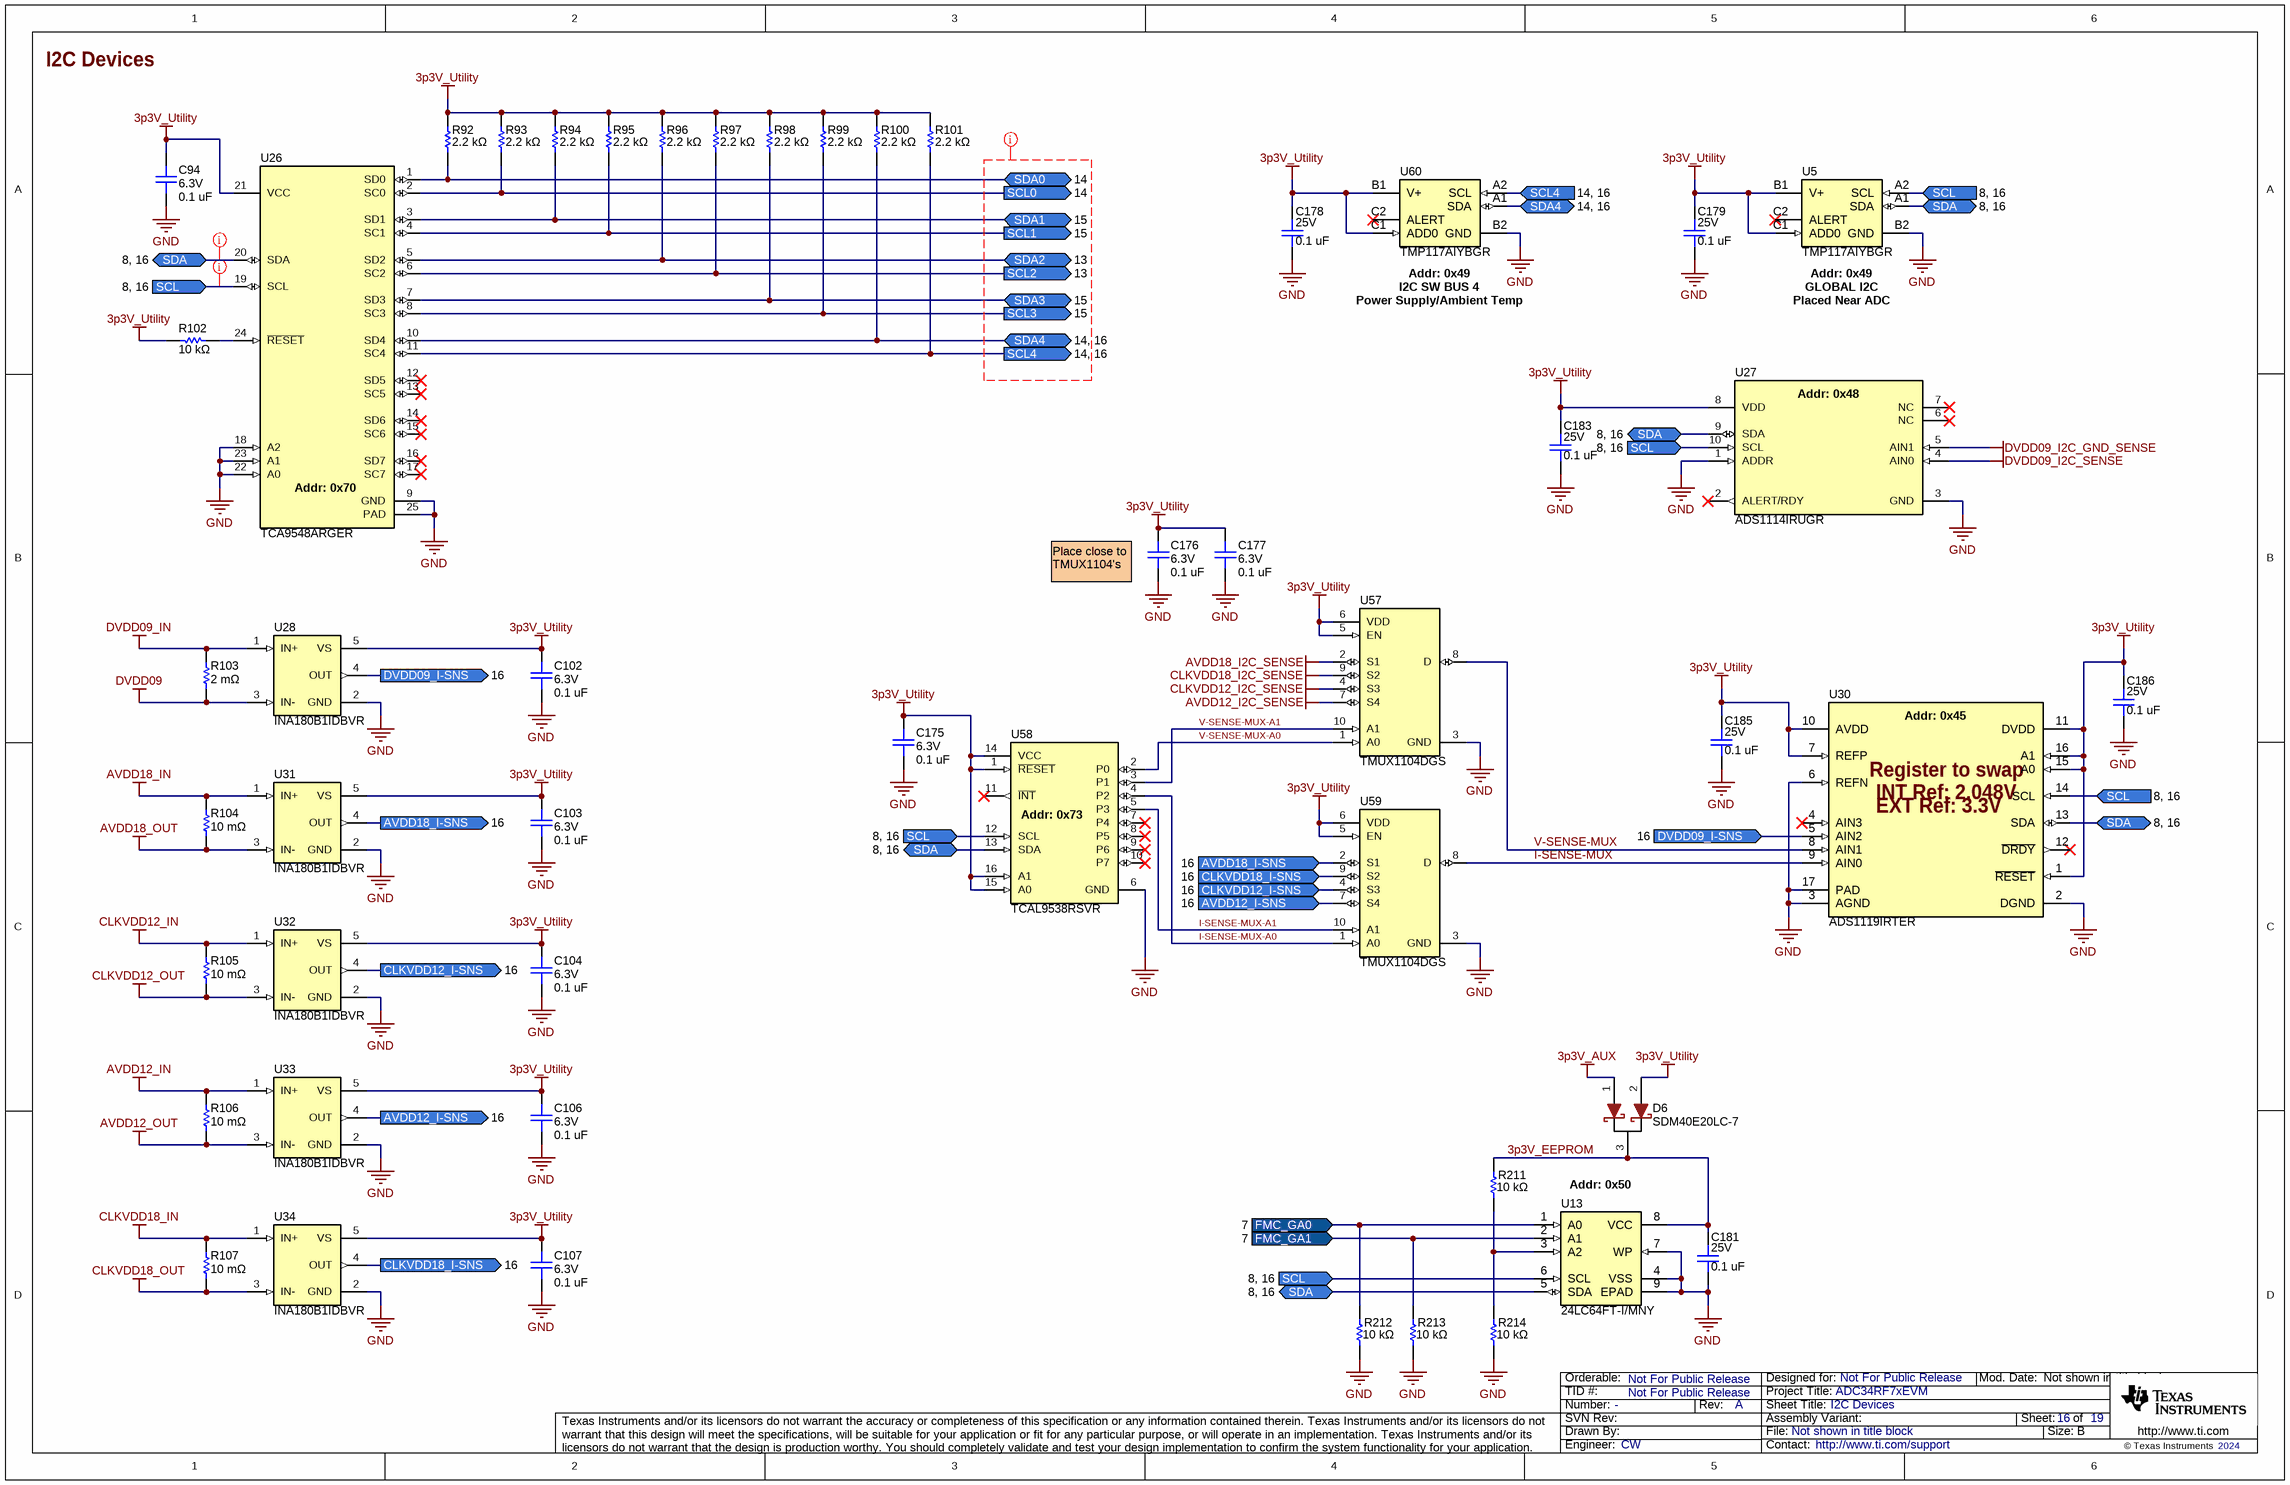
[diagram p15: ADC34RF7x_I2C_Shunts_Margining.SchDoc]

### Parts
C94  value 0.1 uF  Voltage - Rated: 6.3V  [0402L_cap]  (hidden comment: 04026D104KAT4A)
C102  value 0.1 uF  Voltage - Rated: 6.3V  [0402L_cap]  (hidden comment: 04026D104KAT4A)
C103  value 0.1 uF  Voltage - Rated: 6.3V  [0402L_cap]  (hidden comment: 04026D104KAT4A)
C104  value 0.1 uF  Voltage - Rated: 6.3V  [0402L_cap]  (hidden comment: 04026D104KAT4A)
C106  value 0.1 uF  Voltage - Rated: 6.3V  [0402L_cap]  (hidden comment: 04026D104KAT4A)
C107  value 0.1 uF  Voltage - Rated: 6.3V  [0402L_cap]  (hidden comment: 04026D104KAT4A)
C175  value 0.1 uF  Voltage - Rated: 6.3V  [0402L_cap]  (hidden comment: 04026D104KAT4A)
C176  value 0.1 uF  Voltage - Rated: 6.3V  [0402L_cap]  (hidden comment: 04026D104KAT4A)
C177  value 0.1 uF  Voltage - Rated: 6.3V  [0402L_cap]  (hidden comment: 04026D104KAT4A)
C178  value 0.1 uF  Voltage - Rated: 25V  [0201_cap]  (hidden comment: C0603X5R1E104K030BB)
C179  value 0.1 uF  Voltage - Rated: 25V  [0201_cap]  (hidden comment: C0603X5R1E104K030BB)
C181  value 0.1 uF  Voltage - Rated: 25V  [0201_cap]  (hidden comment: C0603X5R1E104K030BB)
C183  value 0.1 uF  Voltage - Rated: 25V  [0201_cap]  (hidden comment: C0603X5R1E104K030BB)
C185  value 0.1 uF  Voltage - Rated: 25V  [0201_cap]  (hidden comment: C0603X5R1E104K030BB)
C186  value 0.1 uF  Voltage - Rated: 25V  [0201_cap]  (hidden comment: C0603X5R1E104K030BB)
D6  SDM40E20LC-7  [SOT-323-DIO]
R92  value 2.2 kΩ  [0201]  (hidden comment: ERJ-1GNF2201C)
R93  value 2.2 kΩ  [0201]  (hidden comment: ERJ-1GNF2201C)
R94  value 2.2 kΩ  [0201]  (hidden comment: ERJ-1GNF2201C)
R95  value 2.2 kΩ  [0201]  (hidden comment: ERJ-1GNF2201C)
R96  value 2.2 kΩ  [0201]  (hidden comment: ERJ-1GNF2201C)
R97  value 2.2 kΩ  [0201]  (hidden comment: ERJ-1GNF2201C)
R98  value 2.2 kΩ  [0201]  (hidden comment: ERJ-1GNF2201C)
R99  value 2.2 kΩ  [0201]  (hidden comment: ERJ-1GNF2201C)
R100  value 2.2 kΩ  [0201]  (hidden comment: ERJ-1GNF2201C)
R101  value 2.2 kΩ  [0201]  (hidden comment: ERJ-1GNF2201C)
R102  value 10 kΩ  [0402L]  (hidden comment: ERJ-PA2F1002X)
R103  value 2 mΩ  [CCS0603FLxLxx]  (hidden comment: CSS0603FT2L00)
R104  value 10 mΩ  [CCS0603FLxLxx]  (hidden comment: CSS0603FT10L0)
R105  value 10 mΩ  [CCS0603FLxLxx]  (hidden comment: CSS0603FT10L0)
R106  value 10 mΩ  [CCS0603FLxLxx]  (hidden comment: CSS0603FT10L0)
R107  value 10 mΩ  [CCS0603FLxLxx]  (hidden comment: CSS0603FT10L0)
R211  value 10 kΩ  [0201]  (hidden comment: ERJ-1GNF1002C)
R212  value 10 kΩ  [0201]  (hidden comment: ERJ-1GNF1002C)
R213  value 10 kΩ  [0201]  (hidden comment: ERJ-1GNF1002C)
R214  value 10 kΩ  [0201]  (hidden comment: ERJ-1GNF1002C)
U5  TMP117AIYBGR  [YBG0006AJAP]
U13  24LC64FT-I/MNY  [TDFN8]
U26  TCA9548ARGER  [RGE0024C]
U27  ADS1114IRUGR  [RUG0010A]
U28  INA180B1IDBVR  [DBV0005A]
U30  ADS1119IRTER  [RTE0016D]
U31  INA180B1IDBVR  [DBV0005A]
U32  INA180B1IDBVR  [DBV0005A]
U33  INA180B1IDBVR  [DBV0005A]
U34  INA180B1IDBVR  [DBV0005A]
U57  TMUX1104DGS  [DQA0010A]
U58  TCAL9538RSVR  [RSV0016A]
U59  TMUX1104DGS  [DQA0010A]
U60  TMP117AIYBGR  [YBG0006AJAP]

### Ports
AVDD12_I-SNS (in, see 16), AVDD12_I-SNS (out, see 16), AVDD18_I-SNS (in, see 16), AVDD18_I-SNS (out, see 16), CLKVDD12_I-SNS (in, see 16), CLKVDD12_I-SNS (out, see 16), CLKVDD18_I-SNS (in, see 16), CLKVDD18_I-SNS (out, see 16), DVDD09_I-SNS (in, see 16), DVDD09_I-SNS (out, see 16), FMC_GA0 (in, see 7), FMC_GA1 (in, see 7), SCL0 (out, see 14), SCL1 (out, see 15), SCL2 (out, see 13), SCL3 (out, see 15), SCL4 (in, see 14, 16), SCL4 (out, see 14, 16), SCL (in, see 8, 16), SDA0 (bidir, see 14), SDA1 (bidir, see 15), SDA2 (bidir, see 13), SDA3 (bidir, see 15), SDA4 (bidir, see 14, 16), SDA (bidir, see 8, 16)

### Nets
3p3V_AUX: D6.1(K)
3p3V_Utility: C94.1 C102.1 C103.1 C104.1 C106.1 C107.1 C175.1 C176.1 C177.1 C178.2 C179.2 C183.2 C185.2 C186.2 D6.2(A) R92.2 R93.2 R94.2 R95.2 R96.2 R97.2 R98.2 R99.2 R100.2 R101.2 R102.2 U5.B1(V+) U5.C1(ADD0) U26.21(VCC) U27.8(VDD) U28.5(VS) U30.1(~{RESET}) U30.7(REFP) U30.10(AVDD) U30.11(DVDD) U30.15(A0) U30.16(A1) U31.5(VS) U32.5(VS) U33.5(VS) U34.5(VS) U57.5(EN) U57.6(VDD) U58.1(~{RESET}) U58.14(VCC) U58.15(A0) U58.16(A1) U59.5(EN) U59.6(VDD) U60.B1(V+) U60.C1(ADD0)
AVDD12_I2C_SENSE: U57.7(S4)
AVDD12_IN: R106.1 U33.1(IN+)
AVDD12_OUT: R106.2 U33.3(IN-)
AVDD18_I2C_SENSE: U57.2(S1)
AVDD18_IN: R104.1 U31.1(IN+)
AVDD18_OUT: R104.2 U31.3(IN-)
CLKVDD12_I2C_SENSE: U57.4(S3)
CLKVDD12_IN: R105.1 U32.1(IN+)
CLKVDD12_OUT: R105.2 U32.3(IN-)
CLKVDD18_I2C_SENSE: U57.9(S2)
CLKVDD18_IN: R107.1 U34.1(IN+)
CLKVDD18_OUT: R107.2 U34.3(IN-)
DVDD09: R103.2 U28.3(IN-)
DVDD09_I2C_GND_SENSE: U27.5(AIN1)
DVDD09_I2C_SENSE: U27.4(AIN0)
DVDD09_IN: R103.1 U28.1(IN+)
GND: C94.2 C102.2 C103.2 C104.2 C106.2 C107.2 C175.2 C176.2 C177.2 C178.1 C179.1 C181.1 C183.1 C185.1 C186.1 R212.2 R213.2 R214.2 U5.B2(GND) U13.4(VSS) U13.7(WP) U13.9(EPAD) U26.9(GND) U26.18(A2) U26.22(A0) U26.23(A1) U26.25(PAD) U27.1(ADDR) U27.3(GND) U28.2(GND) U30.2(DGND) U30.3(AGND) U30.6(REFN) U30.17(PAD) U31.2(GND) U32.2(GND) U33.2(GND) U34.2(GND) U57.3(GND) U58.6(GND) U59.3(GND) U60.B2(GND)
3p3V_EEPROM: C181.2 D6.3(A) R211.1 U13.8(VCC)
AVDD12_I-SNS: U33.4(OUT) U59.7(S4) ; port AVDD12_I-SNS
AVDD18_I-SNS: U31.4(OUT) U59.2(S1) ; port AVDD18_I-SNS
CLKVDD12_I-SNS: U32.4(OUT) U59.4(S3) ; port CLKVDD12_I-SNS
CLKVDD18_I-SNS: U34.4(OUT) U59.9(S2) ; port CLKVDD18_I-SNS
DVDD09_I-SNS: U28.4(OUT) U30.5(AIN2) ; port DVDD09_I-SNS
FMC_GA0: R212.1 U13.1(A0) ; port FMC_GA0
FMC_GA1: R213.1 U13.2(A1) ; port FMC_GA1
I-SENSE-MUX: U30.9(AIN0) U59.8(D)
I-SENSE-MUX-A0: U58.4(P2) U59.1(A0)
I-SENSE-MUX-A1: U58.5(P3) U59.10(A1)
SCL: U5.A2(SCL) U13.6(SCL) U26.19(SCL) U27.10(SCL) U30.14(SCL) U58.12(SCL) ; port SCL
SCL0: R93.1 U26.2(SC0) ; port SCL0
SCL1: R95.1 U26.4(SC1) ; port SCL1
SCL2: R97.1 U26.6(SC2) ; port SCL2
SCL3: R99.1 U26.8(SC3) ; port SCL3
SCL4: R101.1 U26.11(SC4) U60.A2(SCL) ; port SCL4
SDA: U5.A1(SDA) U13.5(SDA) U26.20(SDA) U27.9(SDA) U30.13(SDA) U58.13(SDA) ; port SDA
SDA0: R92.1 U26.1(SD0) ; port SDA0
SDA1: R94.1 U26.3(SD1) ; port SDA1
SDA2: R96.1 U26.5(SD2) ; port SDA2
SDA3: R98.1 U26.7(SD3) ; port SDA3
SDA4: R100.1 U26.10(SD4) U60.A1(SDA) ; port SDA4
V-SENSE-MUX: U30.8(AIN1) U57.8(D)
V-SENSE-MUX-A0: U57.1(A0) U58.2(P0)
V-SENSE-MUX-A1: U57.10(A1) U58.3(P1)
NetR102_1: R102.1 U26.24(~{RESET})
NetR211_2: R211.2 R214.1 U13.3(A2)

Not connected (* = marked no-connect by the designer): U5 C2(ALERT)*; U26 12(SD5)* 13(SC5)* 14(SD6)* 15(SC6)* 16(SD7)* 17(SC7)*; U27 2(ALERT/RDY)* 6(NC)* 7(NC)*; U30 4(AIN3)* 12(~{DRDY})*; U58 7(P4)* 8(P5)* 9(P6)* 10(P7)* 11(~{INT})*; U60 C2(ALERT)*

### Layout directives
net class I2C: (no net found under the mark), SCL, SDA

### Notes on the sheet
- (near U60) Addr: 0x49
- (near U60) I2C SW BUS 4
- Power Supply/Ambient Temp
- (near U5) Addr: 0x49
- (near U5) GLOBAL I2C
- Placed Near ADC
- (near U27) Addr: 0x48
- (near U26) Addr: 0x70
- (near C176) Place close to TMUX1104's
- (near U30) Register to swap
- (near U30) Addr: 0x45
- (near U58) Addr: 0x73
- (near U30) INT Ref: 2.048V
- (near U30) EXT Ref: 3.3V
- Addr: 0x50

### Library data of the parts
C94 C102-C104 C106 C107 C175-C177 = capcc01277: as C235 on sheet ADC34RF7x_Power3_RevA
C178 C179 C181 C183 C185 C186 = capcc01294: CAP CER 0.1UF 25V X5R 0201; Manufacturer: TDK Corporation; SizeZ_mm: 0.33; SizeY_mm: 0.3; CompType: Capacitor Ceramic; SizeX_mm: 0.6; Tolerance: ±10%
D6 = SDM40E20LC-7: Diode Array 1 Pair Common Cathode 20 V 400mA (DC); Manufacturer: Diodes Inc; Text1: 310mV@100mA
R92-R101 = RSMD020100606: RES SMD 2.2K OHM 1% 1/20W 0201; Manufacturer: Panasonic Electronic Components; CompType: Resistor SMD; Power (Watts): 0.05W, 1/20W; Temperature Coefficient: ±200ppm/°C
R102 = RSMD040200311: RES SMD 10K OHM 1% 1/5W 0402; Manufacturer: Panasonic Electronic Components; CompType: Resistor SMD; Power (Watts): 0.2W, 1/5W; Temperature Coefficient: ±100ppm/°C; SizeX_mm: 1; SizeY_mm: 0.5; SizeZ_mm: 0.4
R103 = OtherRs00002: RES SHUNT, 0603, 0.002 OHM, 1%,; Manufacturer: Stackpole Electronics Inc; CompType: Resistor SMD Sense; Power (Watts): 0.333W, 1/3W; Temperature Coefficient: ±150ppm/°C; SizeX_mm: 1.6; SizeY_mm: 0.8; SizeZ_mm: 0.65
R104-R107 = OtherRs00003: RES 0.01 OHM 1% 1/3W 0603; Manufacturer: Stackpole Electronics Inc; CompType: Resistor SMD Sense; Power (Watts): 0.333W, 1/3W; Temperature Coefficient: ±50ppm/°C; SizeX_mm: 1.6; SizeY_mm: 0.8; SizeZ_mm: 0.65
R211-R214 = RSMD020100762: RES SMD 10K OHM 1% 1/20W 0201; Manufacturer: Panasonic Electronic Components; CompType: Resistor SMD; Power (Watts): 0.05W, 1/20W; Temperature Coefficient: ±200ppm/°C
U5 U60 = cmp00348: ±0.1°C accurate digital temperature sensor with integrated NV memory, YBG0006AJAP (DSBGA-6); Manufacturer: Texas Instruments; CompType: Temp Sensor
U13 = cmp00154: EEPROM 64K 8KX8 1.8V SER EE IND 1/4AWP RPO; Manufacturer: Microchip
U26 = CMP-0076018-3: Low-Voltage 8-Channel I2C Switch With Reset, RGE0024C (VQFN-24); Alternate Manufacturer: Texas Instruments; SizeZ_mm: 1.0; SizeY_mm: 4.0; SizeArea_mm2: 16.0; CompType: IC; SizeAreaWB_mm2: 25.0; AEC Category: Q200
U27 = CMP-0081816-1: 16-Bit 860SPS 1-Ch Delta-Sigma ADC With PGA, Oscillator, VREF, Comparator, and I2C, RUG0010A (X2QFN-10); Alternate PartNumber: ADS1114IRUGT; Alternate Manufacturer: Texas Instruments; SizeAreaWB_mm2: 7.5; Rating: Catalog; SizeZ_mm: 0.4; SizeX_mm: 1.5; SizeY_mm: 2; SizeArea_mm2: 3; CompType: IC; AEC Qualified: N; AEC Category: Q200
U28 U31-U34 = INA180B1IDBVR: 26V, 350kHz current sense amplifier; Manufacturer: Texas Instruments; Alt PartNumber: INA180B1IDBVT; CompType: Current Amplifier
U30 = ADS1119IRTER: 16-Bit, 4-Channel, 1-kSPS, Delta-Sigma ADC with I2C Interface, RTE0016D (WQFN-16); Alternate PartNumber: ADS1119IRTET; Alternate Manufacturer: Texas Instruments; SizeAreaWB_mm2: 16; SizeZ_mm: 0.8; SizeX_mm: 3; SizeArea_mm2: 9; AEC Qualified: N; AEC Category: Q200
U57 U59 = TMUX1104DGS: 3-pA on-state leakage current, 5-V, 4:1, 1-channel precision multiplexer; Manufacturer: Texas Instruments; CompType: MUX
U58 = TCAL9538RSVR: Low-voltage 8-bit I²C-bus/SMBus I/O expander with interrupt, reset and agile I/O configuration; Manufacturer: Texas Instruments; CompType: I2C IO Expander

## Sheet ADC34RF7x_uFit_Power.SchDoc: uFit Power
size 431 x 279 mm; Date: Not shown in title block; ApprovedBy: Not shown in title block; CheckedBy: Not shown in title block; Author: Not shown in title block; CompanyName: Not shown in title block; Engineer: Not shown in title block; Organization: Not shown in title block; Address1: Not shown in title block; Address2: Not shown in title block; Address3: Not shown in title block; Address4: Not shown in title block; DocumentNumber: 1; Revision: Use project parameter SCH_Rev; SheetNumber: 17; SheetTotal: 19; PageSetup: Record=PageOptions¦CenterHorizontal=True¦CenterVertical=True¦PrintScale=1.00¦XCorrection=1.00¦YCorrection=1.00¦PrintKind=0¦BorderSize=5000000¦LeftOffset=0¦BottomOffset=0¦Orientation=2¦PaperLength=1000¦PaperWidth=1000¦Scale=100¦PaperSource=15¦PrintQuality=600¦MediaType=1¦DitherType=10¦PaperKind=Letter¦PrintScaleMode=1
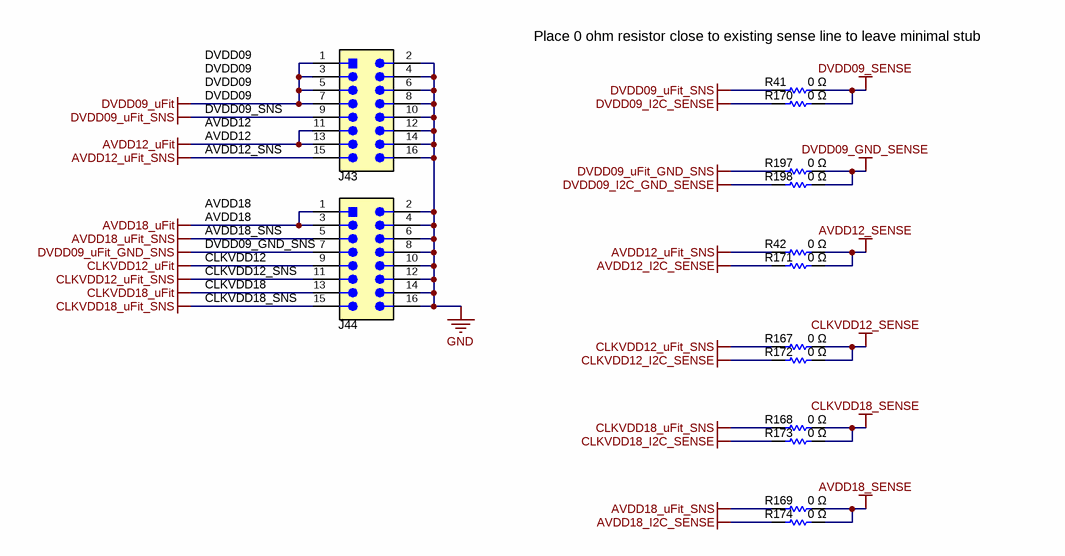
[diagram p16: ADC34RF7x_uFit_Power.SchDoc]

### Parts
J43  Text15: AVDD12_SNS  Text13: AVDD12  Text9: DVDD09_SNS  Text7: DVDD09  [43045-1602]  (hidden comment: 43045-1602)
J44  Text15: CLKVDD18_SNS  Text13: CLKVDD18  Text11: CLKVDD12_SNS  Text9: CLKVDD12  Text7: DVDD09_GND_SNS  Text3: AVDD18  Text5: AVDD18_SNS  [43045-1602]  (hidden comment: 43045-1602)
R41  value 0 Ω  [0201]  (hidden comment: ERJ-1GN0R00C)
R42  value 0 Ω  [0201]  (hidden comment: ERJ-1GN0R00C)
R167  value 0 Ω  [0201]  (hidden comment: ERJ-1GN0R00C)
R168  value 0 Ω  [0201]  (hidden comment: ERJ-1GN0R00C)
R169  value 0 Ω  [0201]  (hidden comment: ERJ-1GN0R00C)
R170  value 0 Ω  [0201]  (hidden comment: ERJ-1GN0R00C)
R171  value 0 Ω  [0201]  (hidden comment: ERJ-1GN0R00C)
R172  value 0 Ω  [0201]  (hidden comment: ERJ-1GN0R00C)
R173  value 0 Ω  [0201]  (hidden comment: ERJ-1GN0R00C)
R174  value 0 Ω  [0201]  (hidden comment: ERJ-1GN0R00C)
R197  value 0 Ω  [0201]  (hidden comment: ERJ-1GN0R00C)
R198  value 0 Ω  [0201]  (hidden comment: ERJ-1GN0R00C)

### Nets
AVDD12_I2C_SENSE: R171.2
AVDD12_SENSE: R42.1 R171.1
AVDD12_uFit: J43.11 J43.13
AVDD12_uFit_SNS: J43.15 R42.2
AVDD18_I2C_SENSE: R174.2
AVDD18_SENSE: R169.1 R174.1
AVDD18_uFit: J44.1 J44.3
AVDD18_uFit_SNS: J44.5 R169.2
CLKVDD12_I2C_SENSE: R172.2
CLKVDD12_SENSE: R167.1 R172.1
CLKVDD12_uFit: J44.9
CLKVDD12_uFit_SNS: J44.11 R167.2
CLKVDD18_I2C_SENSE: R173.2
CLKVDD18_SENSE: R168.1 R173.1
CLKVDD18_uFit: J44.13
CLKVDD18_uFit_SNS: J44.15 R168.2
DVDD09_GND_SENSE: R197.1 R198.1
DVDD09_I2C_GND_SENSE: R198.2
DVDD09_I2C_SENSE: R170.2
DVDD09_SENSE: R41.1 R170.1
DVDD09_uFit: J43.1 J43.3 J43.5 J43.7
DVDD09_uFit_GND_SNS: J44.7 R197.2
DVDD09_uFit_SNS: J43.9 R41.2
GND: J43.2 J43.4 J43.6 J43.8 J43.10 J43.12 J43.14 J43.16 J44.2 J44.4 J44.6 J44.8 J44.10 J44.12 J44.14 J44.16

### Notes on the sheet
- Place 0 ohm resistor close to existing sense line to leave minimal stub

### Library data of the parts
J43 J44 = 43045-1602: 8x2 Headers & Wire Housings Microfit 3.0 RA PTH clip DR Tin 16 Ckt; Manufacturer: Molex
R41 R42 R167-R174 R197 R198 = RSMD020101699: RES SMD 0 OHM JUMPER 1/20W 0201; Manufacturer: Panasonic Electronic Components; CompType: Resistor SMD; Power (Watts): 0.05W, 1/20W

## Sheet ADC34RF7x_Misc_RevA.SchDoc: Misc Hardware/Logos
size 431 x 279 mm; Date: Not shown in title block; ApprovedBy: Not shown in title block; CheckedBy: Not shown in title block; Author: Not shown in title block; CompanyName: Not shown in title block; DrawnBy: CW; Engineer: Not shown in title block; Organization: Not shown in title block; Address1: Not shown in title block; Address2: Not shown in title block; Address3: Not shown in title block; Address4: Not shown in title block; DocumentNumber: 12; Revision: Use project parameter SCH_Rev; SheetNumber: 18; SheetTotal: 19; PageSetup: Record=PageOptions¦CenterHorizontal=True¦CenterVertical=True¦PrintScale=1.00¦XCorrection=1.00¦YCorrection=1.00¦PrintKind=0¦BorderSize=5000000¦LeftOffset=0¦BottomOffset=0¦Orientation=2¦PaperLength=1000¦PaperWidth=1000¦Scale=100¦PaperSource=15¦PrintQuality=600¦MediaType=1¦DitherType=10¦PaperKind=Letter¦PrintScaleMode=1
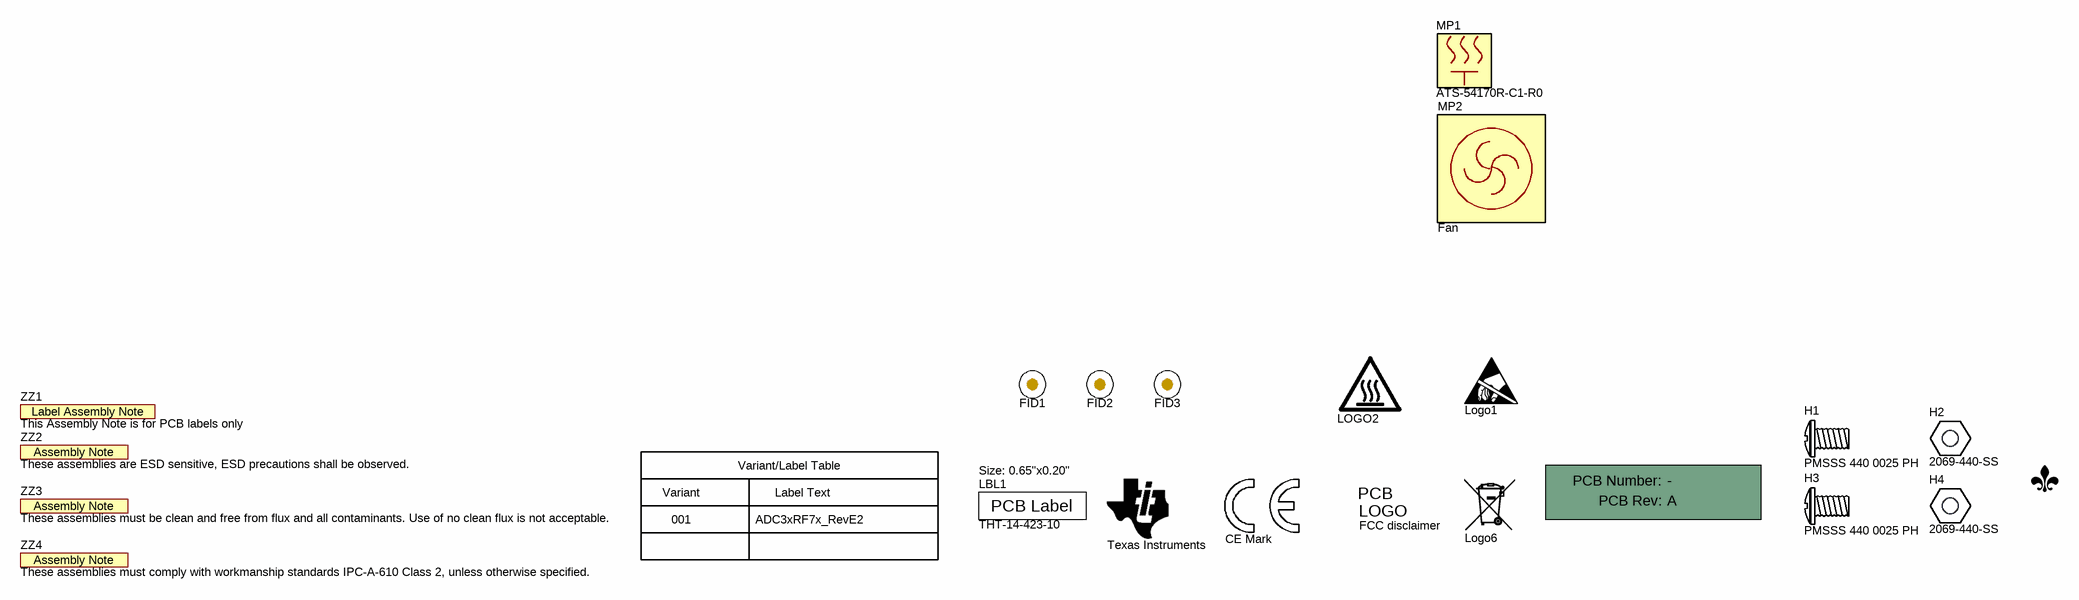
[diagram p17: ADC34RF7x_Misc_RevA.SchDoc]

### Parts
!PCB1  Printed Circuit Board  (value not drawn)  (mechanical)
FID1  Fiducial  [Fiducial10-20]  (value not drawn)  (no BOM)
FID2  Fiducial  [Fiducial10-20]  (value not drawn)  (no BOM)
FID3  Fiducial  [Fiducial10-20]  (value not drawn)  (no BOM)
H1  PMSSS 440 0025 PH  [4400025PH]  (mechanical)
H2  2069-440-SS  [FP-2116-440-AL_STANDOFF_HEX_1-4-MFG]
H3  PMSSS 440 0025 PH  [4400025PH]  (mechanical)
H4  2069-440-SS  [FP-2116-440-AL_STANDOFF_HEX_1-4-MFG]
LBL1  THT-14-423-10  Text1: Size: 0.65"x0.20"  [Label_650x200]
Logo1  ESD Overlay  [ESD_Overlay_Small]  (value not drawn)  (no BOM)
LOGO2  CAUTION HOT SURFACE  [IEC_HotSurface_Small]  (value not drawn)  (no BOM)
Logo3  Texas Instruments  [TI_Stacked_Overlay_Medium]  (no BOM)
LOGO4  CE Mark  [CE_Mark_5mm]  (no BOM)
Logo5  FCC disclaimer  [FCC_disclaimer]  (no BOM)
Logo6  WEEE  [WEEE_Minimum]  (value not drawn)  (no BOM)
Logo12  FDL Logo  [FDL_Small]  (value not drawn)  (no BOM)
MP1  ATS-54170R-C1-R0  [DAC39 - ATS-54170R-C1-R0_BGA_HEATSINK_17p0x17p0mm]
MP2  Fan  [DAC39R - F17HA-05HC_FAN_17p0x17p0mm]
ZZ1  This Assembly Note is for PCB labels only  [AssemblyNoteLabel]  (no BOM)
ZZ2  These assemblies are ESD sensitive, ESD precautions shall be observed.  [AssemblyNote]  (no BOM)
ZZ3  These assemblies must be clean and free from flux and all contaminants. Use of no clean flux is not acceptable.  [AssemblyNote]  (no BOM)
ZZ4  These assemblies must comply with workmanship standards IPC-A-610 Class 2, unless otherwise specified.  [AssemblyNote]  (no BOM)

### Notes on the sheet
- Variant/Label Table
- Variant
- 001
- Label Text
- ADC3xRF7x_RevE2

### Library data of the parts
!PCB1 = cmp00109: CompType: PCB
FID1-FID3 = cmp00099: SymbolCreator: a0412235
H1 H3 = cmp00095: MACHINE SCREW PAN PHILLIPS 4-40; Manufacturer: B&F Fastener Supply
H2 H4 = cmp00097: Hex Standoff Threaded #4-40 Stainless Steel 1.250" (31.75mm) 1 1/4; Manufacturer: RAF Electronic Hardware
LBL1 = cmp00106: Thermal Transfer Printable Labels, 0.650" W x 0.200" H - 10,000 per roll; Manufacturer: Brady; CompType: Label
Logo1 = cmp00317: CompType: Logo
LOGO2 = cmp00100: IEC 61010-1 Hot Surface Warning; CompType: Logo
Logo3 = cmp00104: Texas Instrument Corporate Signature; PartNumber: TI Bug; CompType: Logo
LOGO4 = cmp00103: CE_Mark; CompType: Logo
Logo5 = CMP-0074847-1: FCC_disclaimer; Library Reference: Logo
Logo6 = cmp00101: CompType: Logo
Logo12 = cmp00105: FDL
MP1 = cmp00111: Heat Sink Passive BGA Straight Adhesive 9.3C/W Black Anodized; Manufacturer: Advanced Thermal Solutions
MP2 = cmp00110: Fan Tubeaxial 5VDC Square - 17mm L x 17mm H Sleeve 0.636 CFM (0.018m³/min) 2 Wire Leads; PartNumber: F17HA-05HC; Manufacturer: Nidec Copal
ZZ1 = CMP-0003616-3
ZZ2 = CMP-0077236-1
ZZ3 = CMP-0077237-1
ZZ4 = CMP-0077238-1

## Sheet ADC34RF7x_Revision History.SchDoc: Rev History & Variants
size 431 x 279 mm; Date: Not shown in title block; ApprovedBy: Not shown in title block; CheckedBy: Not shown in title block; Author: Not shown in title block; CompanyName: Not shown in title block; DrawnBy: CW; Engineer: Not shown in title block; Organization: Not shown in title block; Address1: Not shown in title block; Address2: Not shown in title block; Address3: Not shown in title block; Address4: Not shown in title block; DocumentNumber: 13; Revision: Use project parameter SCH_Rev; SheetNumber: 19; SheetTotal: 19; PageSetup: Record=PageOptions¦CenterHorizontal=True¦CenterVertical=True¦PrintScale=1.00¦XCorrection=1.00¦YCorrection=1.00¦PrintKind=0¦BorderSize=5000000¦LeftOffset=0¦BottomOffset=0¦Orientation=2¦PaperLength=1000¦PaperWidth=1000¦Scale=100¦PaperSource=15¦PrintQuality=600¦MediaType=1¦DitherType=10¦PaperKind=Letter¦PrintScaleMode=1
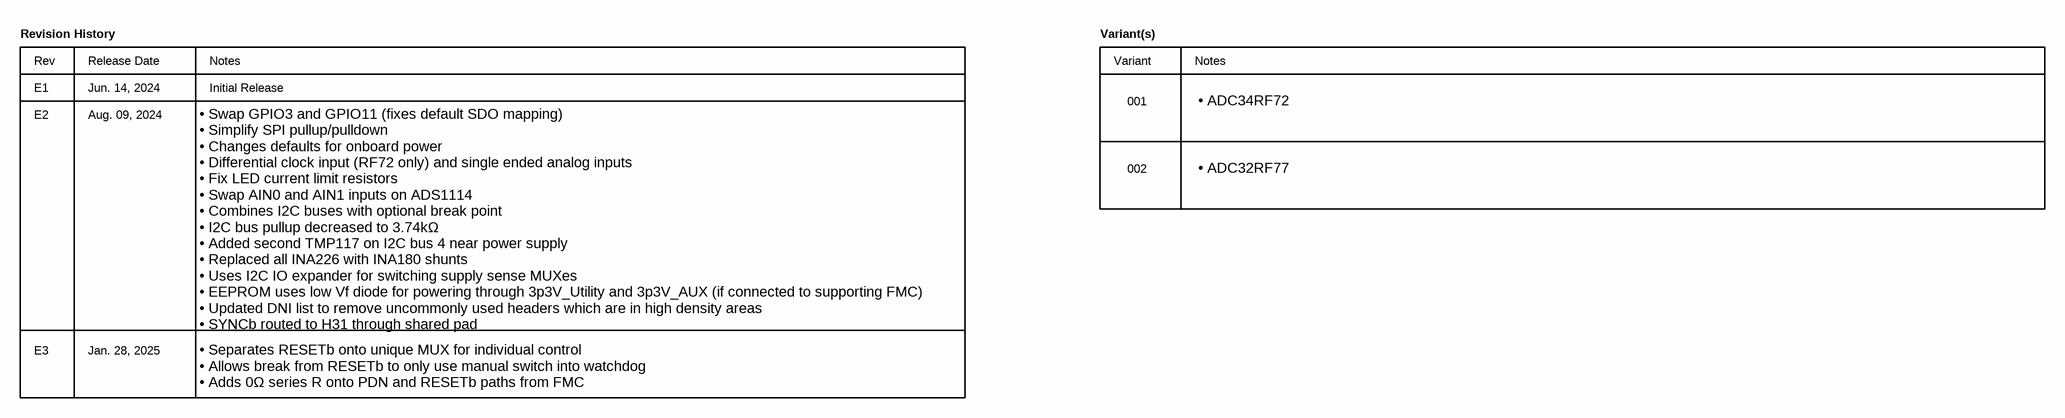
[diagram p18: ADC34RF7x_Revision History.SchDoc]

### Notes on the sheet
- Revision History
- Rev
- Release Date
- Notes
- Variant(s)
- Variant
- E1
- E2
- Jun. 14, 2024
- Aug. 09, 2024
- Initial Release
- 001
- • ADC34RF72
- 002
- • ADC32RF77
- E3
- Jan. 28, 2025
- • Swap GPIO3 and GPIO11 (fixes default SDO mapping)
  • Simplify SPI pullup/pulldown
  • Changes defaults for onboard power
  • Differential clock input (RF72 only) and single ended analog inputs
  • Fix LED current limit resistors
  • Swap AIN0 and AIN1 inputs on ADS1114
  • Combines I2C buses with optional break point
  • I2C bus pullup decreased to 3.74kΩ
  • Added second TMP117 on I2C bus 4 near power supply
  • Replaced all INA226 with INA180 shunts
  • Uses I2C IO expander for switching supply sense MUXes
  • EEPROM uses low Vf diode for powering through 3p3V_Utility and 3p3V_AUX (if connected to supporting FMC)
  • Updated DNI list to remove uncommonly used headers which are in high density areas
  • SYNCb routed to H31 through shared pad
- • Separates RESETb onto unique MUX for individual control
  • Allows break from RESETb to only use manual switch into watchdog
  • Adds 0Ω series R onto PDN and RESETb paths from FMC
